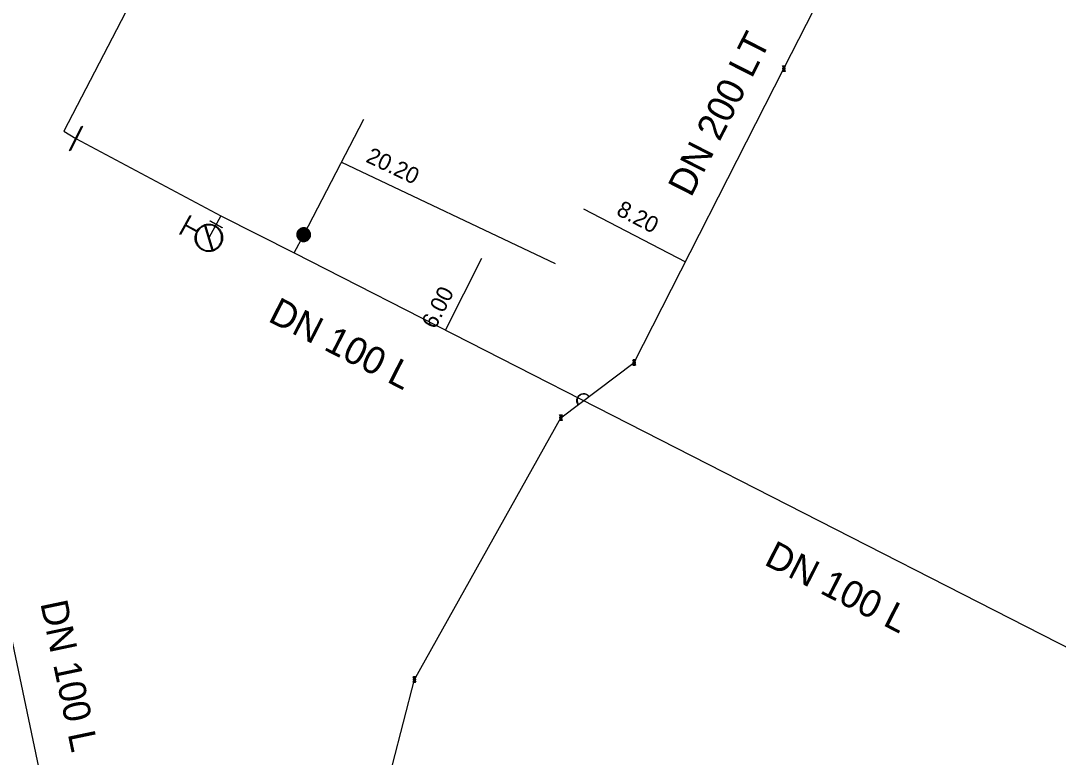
# Model space of a CAD drawing. Extents: x -820257 to -819974, y -1070894 to -1070484.
# Drawn here: x -820185.5 to -820109.2, y -1070621.8 to -1070567.6 of the extents above; entities that cross this region are included whole.
import ezdxf

# ---------------------------------------------------------------- set-up
doc = ezdxf.new("R2010")
doc.units = 0
for name, color, linetype in [('Hyd-odbočka', 7, 'Continuous'), ('Hyd-šoupě', 7, 'Continuous'), ('Hydrant', 7, 'Continuous'), ('Lomový bod vodovodu', 7, 'Continuous'), ('Nepropojené křížení vodovodu', 7, 'Continuous'), ('Oměrka vodovodu', 7, 'Continuous'), ('Oměrka-text', 7, 'Continuous'), ('Přípojka vodovodu', 7, 'Continuous'), ('Přípojkový uzávěr', 7, 'Continuous'), ('Roz-řad', 7, 'Continuous'), ('Roz-řad-popis základní', 7, 'Continuous'), ('Řad-šoupě', 7, 'Continuous')]:
    doc.layers.add(name, color=color, linetype=linetype)

msp = doc.modelspace()

# ---------------------------------------------------------------- linework, layer by layer
at = {"layer": 'Hyd-odbočka'}
msp.add_line((-820170.782, -1070581.978), (-820171.661, -1070583.59), dxfattribs=at)
at = {"layer": 'Hyd-šoupě'}
msp.add_lwpolyline([(-820171.553, -1070582.347), (-820170.675, -1070582.826), (-820170.69, -1070582.853), (-820171.568, -1070582.375), (-820171.553, -1070582.347)], dxfattribs=at)
at = {"layer": 'Hydrant'}
for points in [[(-820172.554, -1070583.138), (-820173.377, -1070582.689), (-820173.736, -1070583.348), (-820173.791, -1070583.318), (-820173.042, -1070581.946), (-820172.987, -1070581.976), (-820173.347, -1070582.635), (-820172.524, -1070583.084)], [(-820171.425, -1070584.499), (-820171.955, -1070582.697)], [(-820171.896, -1070582.68), (-820171.365, -1070584.483)]]:
    msp.add_lwpolyline(points, dxfattribs=at)
for points in [[(-820172.524, -1070583.084), (-820172.404, -1070582.88), (-820172.19, -1070582.741), (-820171.962, -1070582.593), (-820171.687, -1070582.59), (-820171.412, -1070582.587), (-820171.182, -1070582.712), (-820170.954, -1070582.836), (-820170.808, -1070583.066), (-820170.662, -1070583.296), (-820170.66, -1070583.568), (-820170.658, -1070583.841), (-820170.783, -1070584.069), (-820170.907, -1070584.297), (-820171.137, -1070584.443), (-820171.367, -1070584.589), (-820171.639, -1070584.591), (-820171.912, -1070584.592), (-820172.14, -1070584.468), (-820172.369, -1070584.342), (-820172.516, -1070584.109), (-820172.662, -1070583.876), (-820172.661, -1070583.605), (-820172.661, -1070583.351), (-820172.554, -1070583.138)], [(-820171.955, -1070582.697), (-820172.061, -1070582.733), (-820172.157, -1070582.794), (-820172.371, -1070582.933), (-820172.484, -1070583.141), (-820172.597, -1070583.348), (-820172.598, -1070583.604), (-820172.599, -1070583.859), (-820172.463, -1070584.077), (-820172.326, -1070584.295), (-820172.11, -1070584.413), (-820171.895, -1070584.53), (-820171.64, -1070584.527), (-820171.529, -1070584.527), (-820171.425, -1070584.499)], [(-820171.365, -1070584.483), (-820171.264, -1070584.449), (-820171.171, -1070584.389), (-820170.955, -1070584.253), (-820170.838, -1070584.039), (-820170.721, -1070583.825), (-820170.723, -1070583.569), (-820170.724, -1070583.313), (-820170.861, -1070583.098), (-820170.997, -1070582.884), (-820171.212, -1070582.767), (-820171.428, -1070582.649), (-820171.686, -1070582.653), (-820171.796, -1070582.655), (-820171.896, -1070582.68)]]:
    msp.add_open_spline(points, degree=3, dxfattribs=at)
at = {"layer": 'Lomový bod vodovodu'}
for points in [[(-820129.408, -1070571.086), (-820129.47, -1070570.95), (-820129.27, -1070570.95), (-820129.333, -1070571.086)], [(-820129.348, -1070571.079), (-820129.294, -1070570.963), (-820129.448, -1070570.963), (-820129.393, -1070571.079)], [(-820129.333, -1070571.214), (-820129.27, -1070571.35), (-820129.47, -1070571.35), (-820129.408, -1070571.214)], [(-820129.393, -1070571.221), (-820129.448, -1070571.338), (-820129.294, -1070571.338), (-820129.348, -1070571.221)], [(-820129.402, -1070571.203), (-820129.378, -1070571.15), (-820129.402, -1070571.097)], [(-820129.388, -1070571.09), (-820129.37, -1070571.128), (-820129.353, -1070571.09)], [(-820129.353, -1070571.21), (-820129.37, -1070571.172), (-820129.388, -1070571.21)], [(-820129.338, -1070571.097), (-820129.362, -1070571.15), (-820129.338, -1070571.203)], [(-820140.408, -1070592.686), (-820140.47, -1070592.55), (-820140.27, -1070592.55), (-820140.333, -1070592.686)], [(-820140.333, -1070592.814), (-820140.27, -1070592.95), (-820140.47, -1070592.95), (-820140.408, -1070592.814)], [(-820140.348, -1070592.679), (-820140.294, -1070592.563), (-820140.448, -1070592.563), (-820140.393, -1070592.679)], [(-820140.393, -1070592.821), (-820140.448, -1070592.938), (-820140.294, -1070592.938), (-820140.348, -1070592.821)], [(-820140.402, -1070592.803), (-820140.378, -1070592.75), (-820140.402, -1070592.697)], [(-820140.388, -1070592.69), (-820140.37, -1070592.728), (-820140.353, -1070592.69)], [(-820140.353, -1070592.81), (-820140.37, -1070592.772), (-820140.388, -1070592.81)], [(-820140.338, -1070592.697), (-820140.362, -1070592.75), (-820140.338, -1070592.803)], [(-820145.808, -1070596.746), (-820145.87, -1070596.61), (-820145.67, -1070596.61), (-820145.733, -1070596.746)], [(-820145.733, -1070596.874), (-820145.67, -1070597.01), (-820145.87, -1070597.01), (-820145.808, -1070596.874)], [(-820145.748, -1070596.739), (-820145.694, -1070596.623), (-820145.848, -1070596.623), (-820145.793, -1070596.739)], [(-820145.793, -1070596.881), (-820145.848, -1070596.998), (-820145.694, -1070596.998), (-820145.748, -1070596.881)], [(-820145.802, -1070596.863), (-820145.778, -1070596.81), (-820145.802, -1070596.757)], [(-820145.788, -1070596.75), (-820145.77, -1070596.788), (-820145.753, -1070596.75)], [(-820145.753, -1070596.87), (-820145.77, -1070596.832), (-820145.788, -1070596.87)], [(-820145.738, -1070596.757), (-820145.762, -1070596.81), (-820145.738, -1070596.863)], [(-820156.578, -1070615.996), (-820156.64, -1070615.86), (-820156.44, -1070615.86), (-820156.503, -1070615.996)], [(-820156.518, -1070615.989), (-820156.464, -1070615.873), (-820156.618, -1070615.873), (-820156.563, -1070615.989)], [(-820156.572, -1070616.113), (-820156.548, -1070616.06), (-820156.572, -1070616.007)], [(-820156.558, -1070616), (-820156.54, -1070616.038), (-820156.523, -1070616)], [(-820156.508, -1070616.007), (-820156.532, -1070616.06), (-820156.508, -1070616.113)], [(-820156.503, -1070616.124), (-820156.44, -1070616.26), (-820156.64, -1070616.26), (-820156.578, -1070616.124)], [(-820156.563, -1070616.131), (-820156.618, -1070616.248), (-820156.464, -1070616.248), (-820156.518, -1070616.131)], [(-820156.523, -1070616.12), (-820156.54, -1070616.082), (-820156.558, -1070616.12)]]:
    msp.add_lwpolyline(points, dxfattribs=at)
for points in [[(-820129.408, -1070571.214), (-820129.425, -1070571.205), (-820129.435, -1070571.187), (-820129.445, -1070571.17), (-820129.445, -1070571.15), (-820129.445, -1070571.13), (-820129.435, -1070571.113), (-820129.425, -1070571.095), (-820129.408, -1070571.086)], [(-820129.402, -1070571.097), (-820129.416, -1070571.105), (-820129.424, -1070571.119), (-820129.432, -1070571.134), (-820129.432, -1070571.15), (-820129.432, -1070571.166), (-820129.424, -1070571.181), (-820129.416, -1070571.195), (-820129.402, -1070571.203)], [(-820129.393, -1070571.079), (-820129.382, -1070571.075), (-820129.37, -1070571.075), (-820129.359, -1070571.075), (-820129.348, -1070571.079)], [(-820129.348, -1070571.221), (-820129.358, -1070571.225), (-820129.37, -1070571.225), (-820129.382, -1070571.225), (-820129.393, -1070571.221)], [(-820129.353, -1070571.09), (-820129.361, -1070571.088), (-820129.37, -1070571.088), (-820129.379, -1070571.088), (-820129.388, -1070571.09)], [(-820129.388, -1070571.21), (-820129.379, -1070571.212), (-820129.37, -1070571.212), (-820129.361, -1070571.212), (-820129.353, -1070571.21)], [(-820129.338, -1070571.203), (-820129.324, -1070571.195), (-820129.316, -1070571.181), (-820129.308, -1070571.166), (-820129.308, -1070571.15), (-820129.308, -1070571.134), (-820129.316, -1070571.119), (-820129.324, -1070571.105), (-820129.338, -1070571.097)], [(-820129.333, -1070571.086), (-820129.315, -1070571.095), (-820129.305, -1070571.113), (-820129.295, -1070571.13), (-820129.295, -1070571.15), (-820129.295, -1070571.17), (-820129.305, -1070571.187), (-820129.315, -1070571.205), (-820129.333, -1070571.214)], [(-820140.408, -1070592.814), (-820140.425, -1070592.805), (-820140.435, -1070592.787), (-820140.445, -1070592.77), (-820140.445, -1070592.75), (-820140.445, -1070592.73), (-820140.435, -1070592.713), (-820140.425, -1070592.695), (-820140.408, -1070592.686)], [(-820140.402, -1070592.697), (-820140.416, -1070592.705), (-820140.424, -1070592.719), (-820140.432, -1070592.734), (-820140.432, -1070592.75), (-820140.432, -1070592.766), (-820140.424, -1070592.781), (-820140.416, -1070592.795), (-820140.402, -1070592.803)], [(-820140.393, -1070592.679), (-820140.382, -1070592.675), (-820140.37, -1070592.675), (-820140.359, -1070592.675), (-820140.348, -1070592.679)], [(-820140.348, -1070592.821), (-820140.358, -1070592.825), (-820140.37, -1070592.825), (-820140.382, -1070592.825), (-820140.393, -1070592.821)], [(-820140.353, -1070592.69), (-820140.361, -1070592.688), (-820140.37, -1070592.688), (-820140.379, -1070592.688), (-820140.388, -1070592.69)], [(-820140.388, -1070592.81), (-820140.379, -1070592.812), (-820140.37, -1070592.812), (-820140.361, -1070592.812), (-820140.353, -1070592.81)], [(-820140.338, -1070592.803), (-820140.324, -1070592.795), (-820140.316, -1070592.781), (-820140.308, -1070592.766), (-820140.308, -1070592.75), (-820140.308, -1070592.734), (-820140.316, -1070592.719), (-820140.324, -1070592.705), (-820140.338, -1070592.697)], [(-820140.333, -1070592.686), (-820140.315, -1070592.695), (-820140.305, -1070592.713), (-820140.295, -1070592.73), (-820140.295, -1070592.75), (-820140.295, -1070592.77), (-820140.305, -1070592.787), (-820140.315, -1070592.805), (-820140.333, -1070592.814)], [(-820145.808, -1070596.874), (-820145.825, -1070596.865), (-820145.835, -1070596.847), (-820145.845, -1070596.83), (-820145.845, -1070596.81), (-820145.845, -1070596.79), (-820145.835, -1070596.773), (-820145.825, -1070596.755), (-820145.808, -1070596.746)], [(-820145.802, -1070596.757), (-820145.816, -1070596.765), (-820145.824, -1070596.779), (-820145.832, -1070596.794), (-820145.832, -1070596.81), (-820145.832, -1070596.826), (-820145.824, -1070596.841), (-820145.816, -1070596.855), (-820145.802, -1070596.863)], [(-820145.793, -1070596.739), (-820145.782, -1070596.735), (-820145.77, -1070596.735), (-820145.759, -1070596.735), (-820145.748, -1070596.739)], [(-820145.748, -1070596.881), (-820145.758, -1070596.885), (-820145.77, -1070596.885), (-820145.782, -1070596.885), (-820145.793, -1070596.881)], [(-820145.753, -1070596.75), (-820145.761, -1070596.748), (-820145.77, -1070596.748), (-820145.779, -1070596.748), (-820145.788, -1070596.75)], [(-820145.788, -1070596.87), (-820145.779, -1070596.872), (-820145.77, -1070596.872), (-820145.761, -1070596.872), (-820145.753, -1070596.87)], [(-820145.738, -1070596.863), (-820145.724, -1070596.855), (-820145.716, -1070596.841), (-820145.708, -1070596.826), (-820145.708, -1070596.81), (-820145.708, -1070596.794), (-820145.716, -1070596.779), (-820145.724, -1070596.765), (-820145.738, -1070596.757)], [(-820145.733, -1070596.746), (-820145.715, -1070596.755), (-820145.705, -1070596.773), (-820145.695, -1070596.79), (-820145.695, -1070596.81), (-820145.695, -1070596.83), (-820145.705, -1070596.847), (-820145.715, -1070596.865), (-820145.733, -1070596.874)], [(-820156.578, -1070616.124), (-820156.595, -1070616.115), (-820156.605, -1070616.097), (-820156.615, -1070616.08), (-820156.615, -1070616.06), (-820156.615, -1070616.04), (-820156.605, -1070616.023), (-820156.595, -1070616.005), (-820156.578, -1070615.996)], [(-820156.572, -1070616.007), (-820156.586, -1070616.015), (-820156.594, -1070616.029), (-820156.602, -1070616.044), (-820156.602, -1070616.06), (-820156.602, -1070616.076), (-820156.594, -1070616.091), (-820156.586, -1070616.105), (-820156.572, -1070616.113)], [(-820156.563, -1070615.989), (-820156.552, -1070615.985), (-820156.54, -1070615.985), (-820156.529, -1070615.985), (-820156.518, -1070615.989)], [(-820156.523, -1070616), (-820156.531, -1070615.998), (-820156.54, -1070615.998), (-820156.549, -1070615.998), (-820156.558, -1070616)], [(-820156.508, -1070616.113), (-820156.494, -1070616.105), (-820156.486, -1070616.091), (-820156.478, -1070616.076), (-820156.478, -1070616.06), (-820156.478, -1070616.044), (-820156.486, -1070616.029), (-820156.494, -1070616.015), (-820156.508, -1070616.007)], [(-820156.503, -1070615.996), (-820156.485, -1070616.005), (-820156.475, -1070616.023), (-820156.465, -1070616.04), (-820156.465, -1070616.06), (-820156.465, -1070616.08), (-820156.475, -1070616.097), (-820156.485, -1070616.115), (-820156.503, -1070616.124)], [(-820156.518, -1070616.131), (-820156.528, -1070616.135), (-820156.54, -1070616.135), (-820156.552, -1070616.135), (-820156.563, -1070616.131)], [(-820156.558, -1070616.12), (-820156.549, -1070616.122), (-820156.54, -1070616.122), (-820156.531, -1070616.122), (-820156.523, -1070616.12)]]:
    msp.add_open_spline(points, degree=3, dxfattribs=at)
at = {"layer": 'Nepropojené křížení vodovodu'}
for points in [[(-820143.697, -1070595.242), (-820143.722, -1070595.261)], [(-820144.471, -1070595.824), (-820144.496, -1070595.843)]]:
    msp.add_lwpolyline(points, dxfattribs=at)
for points in [[(-820144.496, -1070595.843), (-820144.575, -1070595.739), (-820144.594, -1070595.602), (-820144.612, -1070595.466), (-820144.555, -1070595.343), (-820144.499, -1070595.219), (-820144.398, -1070595.143), (-820144.297, -1070595.068), (-820144.162, -1070595.047), (-820144.028, -1070595.027), (-820143.902, -1070595.082), (-820143.775, -1070595.138), (-820143.697, -1070595.242)], [(-820143.722, -1070595.261), (-820143.796, -1070595.163), (-820143.915, -1070595.111), (-820144.033, -1070595.06), (-820144.159, -1070595.079), (-820144.284, -1070595.097), (-820144.379, -1070595.168), (-820144.473, -1070595.239), (-820144.527, -1070595.355), (-820144.58, -1070595.471), (-820144.563, -1070595.599), (-820144.545, -1070595.727), (-820144.471, -1070595.824)]]:
    msp.add_open_spline(points, degree=3, dxfattribs=at)
at = {"layer": 'Oměrka vodovodu'}
for p, q in [((-820161.902, -1070578.021), (-820146.188, -1070585.474)), ((-820144.094, -1070581.448), (-820136.599, -1070585.345)), ((-820151.608, -1070585.114), (-820154.263, -1070590.36))]:
    msp.add_line(p, q, dxfattribs=at)
at = {"layer": 'Přípojka vodovodu'}
msp.add_lwpolyline([(-820165.379, -1070584.688), (-820164.685, -1070583.357), (-820160.251, -1070574.856)], dxfattribs=at)
at = {"layer": 'Přípojkový uzávěr'}
for points in [[(-820165.129, -1070583.127), (-820165.07, -1070583.015), (-820164.958, -1070582.939), (-820164.845, -1070582.862), (-820164.707, -1070582.858), (-820164.569, -1070582.854), (-820164.453, -1070582.914), (-820164.338, -1070582.974), (-820164.263, -1070583.088), (-820164.188, -1070583.201), (-820164.185, -1070583.337), (-820164.182, -1070583.474), (-820164.242, -1070583.589), (-820164.302, -1070583.704), (-820164.415, -1070583.779), (-820164.529, -1070583.854), (-820164.665, -1070583.858), (-820164.801, -1070583.861), (-820164.916, -1070583.801), (-820165.032, -1070583.74), (-820165.108, -1070583.625), (-820165.183, -1070583.51), (-820165.185, -1070583.374), (-820165.187, -1070583.239), (-820165.129, -1070583.127)], [(-820165.087, -1070583.148), (-820165.14, -1070583.25), (-820165.138, -1070583.373), (-820165.137, -1070583.496), (-820165.068, -1070583.6), (-820164.999, -1070583.705), (-820164.894, -1070583.759), (-820164.79, -1070583.814), (-820164.667, -1070583.811), (-820164.544, -1070583.808), (-820164.441, -1070583.74), (-820164.338, -1070583.671), (-820164.284, -1070583.567), (-820164.229, -1070583.463), (-820164.232, -1070583.339), (-820164.235, -1070583.216), (-820164.303, -1070583.113), (-820164.371, -1070583.01), (-820164.475, -1070582.956), (-820164.58, -1070582.901), (-820164.706, -1070582.905), (-820164.831, -1070582.909), (-820164.933, -1070582.978), (-820165.034, -1070583.047), (-820165.087, -1070583.148)], [(-820165.057, -1070583.164), (-820165.008, -1070583.07), (-820164.914, -1070583.007), (-820164.82, -1070582.943), (-820164.704, -1070582.939), (-820164.588, -1070582.935), (-820164.491, -1070582.986), (-820164.394, -1070583.037), (-820164.331, -1070583.131), (-820164.269, -1070583.226), (-820164.266, -1070583.34), (-820164.263, -1070583.455), (-820164.314, -1070583.552), (-820164.364, -1070583.648), (-820164.459, -1070583.711), (-820164.554, -1070583.774), (-820164.668, -1070583.777), (-820164.782, -1070583.779), (-820164.878, -1070583.729), (-820164.976, -1070583.678), (-820165.039, -1070583.582), (-820165.103, -1070583.486), (-820165.104, -1070583.372), (-820165.106, -1070583.258), (-820165.057, -1070583.164)], [(-820165.018, -1070583.185), (-820165.09, -1070583.323), (-820165.043, -1070583.471), (-820164.996, -1070583.618), (-820164.858, -1070583.69), (-820164.72, -1070583.762), (-820164.572, -1070583.715), (-820164.424, -1070583.669), (-820164.353, -1070583.532), (-820164.281, -1070583.393), (-820164.327, -1070583.245), (-820164.374, -1070583.097), (-820164.511, -1070583.025), (-820164.649, -1070582.953), (-820164.797, -1070582.999), (-820164.945, -1070583.045), (-820165.018, -1070583.185)], [(-820164.977, -1070583.206), (-820164.914, -1070583.084), (-820164.785, -1070583.044), (-820164.655, -1070583.004), (-820164.535, -1070583.067), (-820164.414, -1070583.13), (-820164.373, -1070583.259), (-820164.332, -1070583.389), (-820164.395, -1070583.51), (-820164.459, -1070583.631), (-820164.588, -1070583.671), (-820164.717, -1070583.712), (-820164.838, -1070583.649), (-820164.959, -1070583.586), (-820165, -1070583.457), (-820165.041, -1070583.327), (-820164.977, -1070583.206)], [(-820164.942, -1070583.224), (-820164.998, -1070583.331), (-820164.962, -1070583.445), (-820164.926, -1070583.558), (-820164.82, -1070583.614), (-820164.714, -1070583.669), (-820164.6, -1070583.633), (-820164.486, -1070583.598), (-820164.431, -1070583.491), (-820164.375, -1070583.385), (-820164.411, -1070583.271), (-820164.447, -1070583.157), (-820164.553, -1070583.102), (-820164.659, -1070583.047), (-820164.773, -1070583.082), (-820164.887, -1070583.117), (-820164.942, -1070583.224)], [(-820164.907, -1070583.242), (-820164.858, -1070583.149), (-820164.76, -1070583.119), (-820164.661, -1070583.088), (-820164.569, -1070583.136), (-820164.477, -1070583.184), (-820164.446, -1070583.283), (-820164.416, -1070583.381), (-820164.464, -1070583.474), (-820164.511, -1070583.565), (-820164.61, -1070583.596), (-820164.708, -1070583.627), (-820164.8, -1070583.579), (-820164.892, -1070583.531), (-820164.924, -1070583.433), (-820164.955, -1070583.335), (-820164.907, -1070583.242)], [(-820164.866, -1070583.264), (-820164.905, -1070583.339), (-820164.88, -1070583.419), (-820164.855, -1070583.499), (-820164.78, -1070583.538), (-820164.705, -1070583.577), (-820164.625, -1070583.552), (-820164.545, -1070583.526), (-820164.506, -1070583.452), (-820164.467, -1070583.377), (-820164.492, -1070583.297), (-820164.517, -1070583.217), (-820164.592, -1070583.178), (-820164.667, -1070583.138), (-820164.747, -1070583.164), (-820164.827, -1070583.189), (-820164.866, -1070583.264)], [(-820164.835, -1070583.28), (-820164.803, -1070583.217), (-820164.736, -1070583.197), (-820164.67, -1070583.176), (-820164.608, -1070583.208), (-820164.546, -1070583.241), (-820164.525, -1070583.307), (-820164.504, -1070583.374), (-820164.536, -1070583.436), (-820164.569, -1070583.498), (-820164.635, -1070583.519), (-820164.701, -1070583.54), (-820164.764, -1070583.507), (-820164.826, -1070583.475), (-820164.847, -1070583.408), (-820164.868, -1070583.342), (-820164.835, -1070583.28)], [(-820164.796, -1070583.3), (-820164.82, -1070583.346), (-820164.804, -1070583.395), (-820164.789, -1070583.444), (-820164.743, -1070583.468), (-820164.697, -1070583.492), (-820164.648, -1070583.477), (-820164.598, -1070583.461), (-820164.574, -1070583.416), (-820164.55, -1070583.369), (-820164.566, -1070583.32), (-820164.581, -1070583.271), (-820164.627, -1070583.247), (-820164.673, -1070583.223), (-820164.722, -1070583.238), (-820164.772, -1070583.253), (-820164.796, -1070583.3)], [(-820164.755, -1070583.322), (-820164.739, -1070583.292), (-820164.709, -1070583.283), (-820164.679, -1070583.273), (-820164.649, -1070583.289), (-820164.621, -1070583.304), (-820164.611, -1070583.334), (-820164.601, -1070583.365), (-820164.616, -1070583.394), (-820164.631, -1070583.423), (-820164.662, -1070583.432), (-820164.693, -1070583.442), (-820164.721, -1070583.427), (-820164.751, -1070583.412), (-820164.76, -1070583.381), (-820164.77, -1070583.35), (-820164.755, -1070583.322)], [(-820164.727, -1070583.336), (-820164.736, -1070583.354), (-820164.73, -1070583.372), (-820164.725, -1070583.39), (-820164.707, -1070583.399), (-820164.69, -1070583.408), (-820164.671, -1070583.403), (-820164.653, -1070583.397), (-820164.644, -1070583.38), (-820164.635, -1070583.362), (-820164.64, -1070583.344), (-820164.646, -1070583.325), (-820164.664, -1070583.316), (-820164.681, -1070583.307), (-820164.7, -1070583.313), (-820164.718, -1070583.318), (-820164.727, -1070583.336)]]:
    msp.add_open_spline(points, degree=3, dxfattribs=at)
at = {"layer": 'Roz-řad'}
msp.add_line((-820181.435, -1070576.285), (-820170.782, -1070581.978), dxfattribs=at)
for points in [[(-820149.629, -1070512.816), (-820182.322, -1070575.745), (-820181.435, -1070576.285)], [(-820173.82, -1070657.97), (-820165.56, -1070640.89), (-820158.15, -1070622.33), (-820156.54, -1070616.06), (-820145.77, -1070596.81), (-820140.37, -1070592.75), (-820129.37, -1070571.15), (-820123.84, -1070560.28), (-820117.608, -1070563.82), (-820117.26, -1070563.21)], [(-820170.782, -1070581.978), (-820165.379, -1070584.688), (-820101.033, -1070617.521), (-820097.577, -1070619.176)], [(-820192.294, -1070583.934), (-820183.322, -1070626.593), (-820174.41, -1070657.75)]]:
    msp.add_lwpolyline(points, dxfattribs=at)
at = {"layer": 'Řad-šoupě'}
msp.add_lwpolyline([(-820180.955, -1070575.407), (-820181.859, -1070577.191), (-820181.915, -1070577.163), (-820181.01, -1070575.379), (-820180.955, -1070575.407)], dxfattribs=at)

# ---------------------------------------------------------------- texts
at = {"layer": 'Oměrka-text'}
for s, rotation, p in [('20.20', 334.62546, (-820160.188, -1070577.974)), (' 8.20', 332.52465, (-820142.162, -1070581.654)), (' 6.00', 63.15605, (-820155.206, -1070590.756))]:
    msp.add_text(s, height=1.2, rotation=rotation, dxfattribs=at).set_placement(p)
at = {"layer": 'Roz-řad-popis základní'}
for s, rotation, p in [('DN 200 LT', 63.01212, (-820136.194, -1070580.672)), ('DN 100 L', 332.96675, (-820167.39, -1070589.683)), ('DN 100 L', 332.96675, (-820130.9, -1070607.576)), ('DN 100 L', 281.8773, (-820184.063, -1070610.447))]:
    msp.add_text(s, height=2, rotation=rotation, dxfattribs=at).set_placement(p)

doc.saveas('drawing.dxf')
